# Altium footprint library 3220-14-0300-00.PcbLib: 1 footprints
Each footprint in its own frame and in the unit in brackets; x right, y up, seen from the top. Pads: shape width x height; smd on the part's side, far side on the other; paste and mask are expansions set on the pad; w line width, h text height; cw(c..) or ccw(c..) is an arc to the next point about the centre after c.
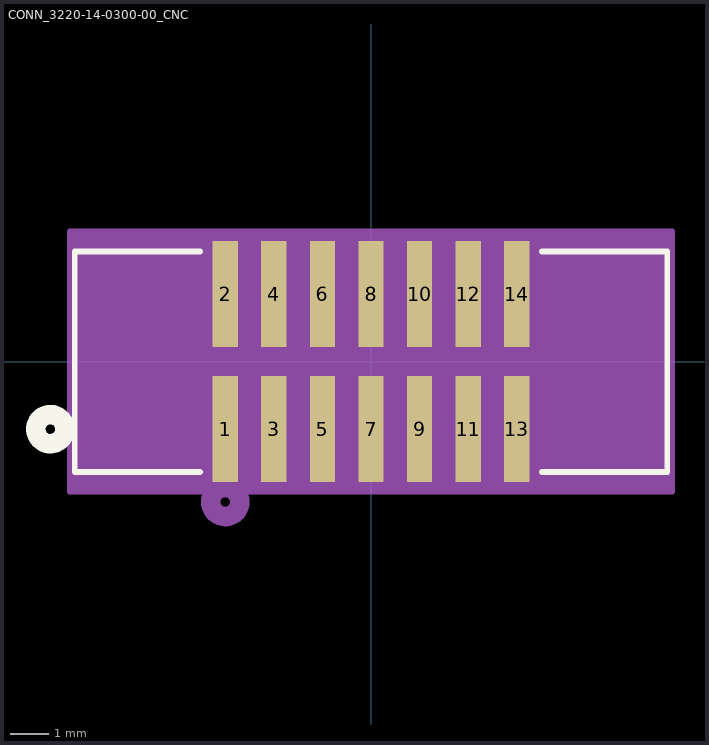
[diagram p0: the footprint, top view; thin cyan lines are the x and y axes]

## CONN_3220-14-0300-00_CNC [mil]
pads (14):
  rect 26x109 smd paste+0 mask+0: 1(-150,-69.49) 2(-150,69.49) 3(-100,-69.49) 4(-100,69.49) 5(-50,-69.49) 6(-50,69.49) 7(0,-69.49) 8(0,69.49) 9(50,-69.49) 10(50,69.49) 11(100,-69.49) 12(100,69.49) 13(150,-69.49) 14(150,69.49)
Top Overlay:
  circle w20: c-330,-69.49 r15
  lines w6: -176.1,-113.5 -305,-113.5 -305,113.5 -176.1,113.5 ; 176.1,-113.5 305,-113.5 305,113.5 176.1,113.5
Bottom Overlay:
  circle w20: c-330,-69.49 r15
Mechanical 13:
  circle w20: c-150,-144.49 r15
  lines w1: -300,-108.5 300,-108.5 300,108.5 -300,108.5 -300,-108.5
Mechanical 15:
  region: 310,133.99 -310,133.99 -310,-133.99 310,-133.99
  lines w6: -310,-133.99 -310,133.99 310,133.99 310,-133.99 -310,-133.99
